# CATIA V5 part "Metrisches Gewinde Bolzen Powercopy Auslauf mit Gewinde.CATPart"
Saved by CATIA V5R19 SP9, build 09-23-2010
Part number: Metrisches Gewinde
Bounding box of the stored display mesh (mm): x -4 to 4, y -4 to 4, z 0 to 30
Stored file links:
  E:\Markus\CATIA\_Standards\Metrisches Gewinde Bolzen Powercopy Auslauf mit Gewinde.CATPart
  E:\Markus\CATIA\_Standards\Metrisches Gewinde.txt
  Unbenannt-M8x20-Gewindestange.CATPart
  d:\Program Files\Dassault Systemes\B19\win_b64\reffiles\standard\MetricThickPitch.txt
  E:\Markus\CATIA\_Standards\Metrisches Gewinde 2.CATPart
  E:\Markus\CATIA\_Standards\Metrisches Gewinde Mutter Powercopy.CATPart
  E:\Markus\CATIA\_Standards\Metrisches Gewinde Bolzen Powercopy Auslauf bestehendes Gewinde.CATPart
  d:\Program Files\Dassault Systemes\B19\win_b64\reffiles\standard\Rohrgewinde Whitworth DINISO228.txt
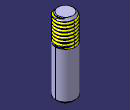
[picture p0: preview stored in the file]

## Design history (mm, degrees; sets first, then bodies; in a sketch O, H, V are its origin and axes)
Parameters
  DurchmesserBolzen = 8 mm
Set1 "Gewinde Bolzen mit Auslauf"
  Extract1 "AbleitenStirnfläche": ExtractElem end face of Pad1
  Boundary1 "BegrenzungStirnfläche": Boundary Extract1
  Point1 "MitteGewinde": type Center, Curve Boundary1
  Line1 "GewindeAchse": type PtDir, RefPoint Point1, Direction Extract1, Start 0, End 10 {= Thread1.Depth + `VerlängerungGewinde`}
  Point2 "EndeGewinde": type OnCurve, Support Line1, Ratio 1
  Line2 "Y-Richtung": type PtDir, RefPoint Point1, Direction (0, 1, 0), Start 0, End 4
  Line3 "PlaneRichtung": stored without definition
  Plane1 "SkizzenEbene": type 2Lines, Element1 Line1, Element2 Line3
  Line4 "LinieStartHelix": type Angle, RefPoint Point2, Curve Line1, Support Plane1, Start 0, End 4 {= Thread1.Diameter /2}, Angle 90
  Point3 "StartpunktHelix": type OnCurve, Support Line4, Ratio 1
  Helix1 "HelixGewinde": Direction Line1, RefPoint Point3, Pitch 1.25 {= Thread1.Pitch}, Height 11.25 {= Thread1.Depth + Thread1.Pitch   + `VerlängerungGewinde`}, TaperAngle 0
  Sketch1 "GewindeSkizze" on Plane1, origin (0, 0, 20), H (0, 1, 0), V (0, 0, -1)
    construction line L1 (5, 0.625) -> (4.0451, 0.625)
    arc A1 centre (3.4136, 0) radius 0.1804 from (3.3234, 0.1562) to (3.3234, -0.1562) ccw
    point P3 (3.4136, 0)
    line L2 (3.3234, -0.1562) -> (4, -0.5469)
    construction line L3 (5, -0.7031) -> (5, 0.625)
    line L4 (4, 0.5469) -> (3.3234, 0.1562)
    construction line L5 (4, -0.7031) -> (5, -0.7031)
    construction arc A2 centre (3.9549, 0.625) radius 0.0902 from (4, 0.5469) to (4.0451, 0.625) ccw
    point P6 (4, 0.5469)
    point P7 (3.9549, 0.625)
    arc A3 centre (3.9549, -0.625) radius 0.0902 from (4, -0.7031) to (4, -0.5469) ccw
    construction line L6 (3.9549, 0.625) -> (3.9549, -0.625)
    construction line L7 (4, -0.7031) -> (3.6747, -0.891)
    angle L2 L4 = 60
    length L6 = 1.25 {= Thread1.Pitch}
    radius A1 = 0.1804 {= 0.1443*Thread1.Pitch}
    distance A1 V = 3.2332 {= (Thread1.Diameter  -1.2269*Thread1.Pitch )/2+`Set1.Gewinde Offset`}
    radius A2 = 0.0902 (reference)
    radius A3 = 0.0902 (reference)
    distance V P6 = 4 {= Thread1.Diameter /2+`Set1.Gewinde Offset`}
    length L1 = 0.9549
    distance L1 H = 0.625 {= Thread1.Pitch /2}
    tangency: A1 L4, L2 A1, A2 L4, A3 L2, L7 A3
    vertical: L3 V, L6 V
    coincidence: P3 H, P7 L1
    symmetry: L4 L2 H
    horizontal: L5 H, L1 H
    parallelism: L7 L4
  Extract2: ExtractElem Sketch1.A3
  Extract3: ExtractElem Sketch1.L2
  Extract4: ExtractElem Sketch1.A1
  Extract5: ExtractElem Sketch1.L4
  Join1 "GewindeProfilOben": Elements (Extract2; Extract3)
  Join2 "GewindeProfilUnten": Elements (Extract4; Extract5)
  Sweep1 "GewindeOben": type Unspec, Profile Join1, Guide Helix1, AngleRef 0, PullingDir Line1
  Sweep2 "GewindeUnten": type Unspec, Profile Join2, Guide Helix1, AngleRef 0, PullingDir Line1
  Trim1 "Gewinde": Trimmed (Sweep1; Sweep2)
  Helix2 "HelixAuslauf": Direction Line1, RefPoint Point3, Pitch 1.25 {= Thread1.Pitch}, Height 1.1875 {= Thread1.Pitch * 0.95}, TaperAngle 62
  Sweep3 "Auslauf": type Unspec, Profile Sketch1, Guide Helix2, AngleRef 0, PullingDir Line1
  Extrapol1 "ExtrapolGewinde": ToExtrapol edge of Sweep2, Support Trim1, Length 2.3509 {= Thread1.Pitch  *tan(Helix2.TaperAngle )}
  Extrapol2 "ExtrapolAuslauf": ToExtrapol edge of Sweep3, Support Sweep3, Length 2
  Trim2 "GewindeMitAuslauf": Trimmed (Extrapol1; Extrapol2)
  Fillet1 "GewindeMitAuslaufRund": radius 0.0601 {= 0.1443 * Thread1.Pitch /3}, on edge [face of Extrapol1 | face of Sweep3]
  Sketch2 "Beschnitt" on Plane1, origin (0, 0, 20), H (0, 1, 0), V (0, 0, -1)
    point P1 (4, 0.5469)
    line L1 (0, 0.5469) -> (6, 0.5469)
    point P2 (0, 0.5469)
    point P3 (6, 0.5469)
    reference projected line E1 (4, 0.5469) -> (3.3234, 0.1562) from Sketch1.L4
    distance V P1 = 4 {= max(Thread1.Diameter /2, Thread1.Diameter /2+`Set1.Gewinde Offset` )}
    distance P3 V = 6 {= Sketch2.distance(V P1) *1.5}
    distance L1 H = 0
    coincidence: P2 V, P1 L1, P1 E1
    horizontal: L1 H
  Revol1: Element1 Sketch2, Line Line1, Angle1 360
  Trim3 "GewindeGekuerzt": Trimmed (Fillet1; Revol1)
  DatumSurface1 "BeschnittFlaecheLinksRechts"
Body1 "Bolzen" (main body)
  Sketch3 on xy-plane, origin (0, 0, 0), H (1, 0, 0), V (0, 1, 0)
    circle A1 centre (0, 0) radius 4
    radius A1 = 4 {= DurchmesserBolzen /2}
  Pad1: profile Sketch3, direction (0, 0, 1), length 30
  Chamfer1 "Fase": length 1, angle 45, on end face of Pad1; start face of Pad1
  Thread1 "Gewinde": "M8", diameter 8, depth 10, pitch 1.25, on face of Pad1 from Sketch3.A1, from end face of Pad1
  Split1 "TrennenGewinde": SplitPlane DatumSurface1
Relations
  Line3 = line(Point1  ,direction(List(int(mod(angle(Line1  ,Line2 )/1deg ,180)) )->IndexOf(0,0)*10mm ,mod(angle(Line1  ,Line2  )/1deg ,180)*10mm ,0mm) ,0mm,10mm,true)
  DatumSurface1 = List( Trim3  , symmetry( Trim3 ,Plane1 ) )->GetItem(1 +List(Thread1.RotationSide )->IndexOf(true,0)   )
  Thread1.ThreadDescription = "M"+DurchmesserBolzen  *1000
